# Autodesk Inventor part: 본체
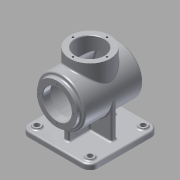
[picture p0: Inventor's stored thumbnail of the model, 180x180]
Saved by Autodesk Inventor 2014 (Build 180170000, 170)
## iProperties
Created: 2015-07
Part Number: 본체
Material: 알루미늄 6061
Document SubType Name: Modeling
Designer: L-10
Density: 2.71 g/cm^3
Appearance: 알루미늄 - 평지
Mass: 1277.36 g
Surface Area: 1268.17 cm^2
Volume: 471.35 cm^3
Author: L-10
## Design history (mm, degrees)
sketch "스케치2"
  geometry: C1 r 45 at (0, 0); 1 further point
  constraints: 1 centre point, 1 coincident
  dimensions: "d0" = 90 diameter of C1
extrude "돌출1" new body sketch "스케치2" stored distance "d1" = 110; taper "d2" = 0 deg
node "작업 평면1"
sketch "스케치3"
  geometry: L1 (-65, -65)-(65, -65); L2 (65, -65)-(65, 65); L3 (65, 65)-(-65, 65); L4 (-65, 65)-(-65, -65); 3 further points
  constraints: 8 end point, 2 midpoint, 2 parallel, 1 horizontal, 1 horizontal alignment, 1 perpendicular, 1 vertical alignment
  dimensions: "d4" = 130 distance of L2.end L3.end; "d5" = 130 distance of L3.end L1.start
extrude "돌출2" join sketch "스케치3" distance "d6" = 10; taper "d7" = 0 deg
sketch "스케치4"
  geometry: C1 r 45 at (0, 0) reference; C2 r 38 at (0, 0)
  constraints: 1 centre point, 1 coincident
  dimensions: "d8" = 76 diameter of C2
extrude "돌출3" join sketch "스케치4" distance "d9" = 7; taper "d10" = 0 deg
sketch "스케치5"
  geometry: L1 (-65, 65)-(-65, -65) reference; L2 (-5, 45)-(-5, 5); L3 (-5, 5)-(-45, 5); L4 (-45, 5)-(-45, -5); L5 (-45, -5)-(-5, -5); L6 (-5, -5)-(-5, -45); L7 (-5, -45)-(5, -45); L8 (5, -45)-(5, -5); L9 (5, -5)-(45, -5); L10 (45, -5)-(45, 5); L11 (45, 5)-(5, 5); L12 (5, 5)-(5, 45); L13 (5, 45)-(-5, 45); 3 further points
  constraints: 24 end point, 9 parallel, 6 collinear, 2 midpoint, 1 horizontal alignment, 1 perpendicular, 1 vertical alignment
  dimensions: "d11" = 10 distance of L9.end L10.end; "d12" = 10 distance of L12.end L2.start; "d13" = 90 distance between parallel lines of L7 L13; "d14" = 90 distance between parallel lines of L10 L4; "d15" = 45 distance from line of L4 point (0, 0) (= 0.5 x d14); "d16" = 45 distance from line of point (0, 0) L13 (= 0.5 x d13)
extrude "돌출4" join sketch "스케치5" stored distance "d17" = 7; taper "d18" = 0 deg
node "작업 평면2"
sketch "스케치6"
  geometry: C1 r 38 at (0, 0); 1 further point
  constraints: 1 centre point, 1 coincident
  dimensions: "d20" = 76 diameter of C1
extrude "돌출5" join sketch "스케치6" stored distance "d21" = 7; taper "d22" = 0 deg
fillet "모깎기1" dims "d23" = 15
sketch "스케치7"
  geometry: C1 r 7.5 at (50, -50); C2 r 7.5 at (50, 50); A1 r 15 centre (50, -50) between (50, -65) and (65, -50) reference; A2 r 15 centre (50, 50) between (65, 50) and (50, 65) reference; 1 further point
  constraints: 2 centre point, 2 coincident
  dimensions: "d24" = 15 diameter of C1; "d25" = 15 diameter of C2; "d26" = 100 distance of C2.centre C1.centre (derived)
extrude "돌출6" join sketch "스케치7" distance "d27" = 3; taper "d28" = 0 deg
hole "구멍1" diameter "d31" = 10; stored, may be unused: countersink angle "d35" = 90 deg, drill point angle "d37" = 118 deg; dims "d29" = 10, "d30" = 10, "d32" = 6, "d33" = 4, "d34" = 2, "d36" = 8
hole "구멍2" diameter "d40" = 10; stored, may be unused: countersink angle "d44" = 90 deg, drill point angle "d46" = 118 deg; dims "d38" = 10, "d39" = 10, "d41" = 6, "d42" = 4, "d43" = 2, "d45" = 8
hole "구멍3" diameter "d49" = 10; stored, may be unused: countersink angle "d53" = 90 deg, drill point angle "d55" = 118 deg; dims "d47" = 10, "d48" = 10, "d50" = 6, "d51" = 4, "d52" = 2, "d54" = 8
hole "구멍4" diameter "d58" = 10; stored, may be unused: countersink angle "d62" = 90 deg, drill point angle "d64" = 118 deg; dims "d56" = 10, "d57" = 10, "d59" = 6, "d60" = 4, "d61" = 2, "d63" = 8
sketch "스케치8"
  geometry: L1 (-62, 0)-(55, 0); L2 (-62, 38)-(-62, -38) reference; L3 (55, -45)-(55, 45) reference; L4 (-62, 27)-(-48, 27); L5 (-48, 27)-(-48, 40); L6 (-48, 40)-(48, 40); L7 (48, 40)-(48, 0); 2 further points
  constraints: 10 end point, 3 point on line, 2 midpoint, 2 parallel, 2 perpendicular, 1 horizontal, 1 horizontal alignment
  dimensions: "d65" = 80 diameter of L6 L1; "d66" = 7 distance between parallel lines of L3 L7; "d67" = 14 distance between parallel lines of L2 L5; "d68" = 54 diameter of L4 L1
revolve "회전1" sketch "스케치8" stored, may be unused: angle "d69" = 90 deg
hole "구멍5" diameter "d72" = 54; stored, may be unused: countersink angle "d76" = 90 deg, drill point angle "d78" = 118 deg; dims "d70" = 10, "d71" = 10, "d73" = 6, "d74" = 4, "d75" = 2, "d77" = 8
fillet "모깎기2" dims "d79" = 3
chamfer "모따기1" distance "d80" = 1; stored, may be unused: second distance "d81" = 2, angle "d82" = 45 deg
sketch "스케치9"
  geometry: C1 r 27 at (0, 0) reference; 1 further point
  constraints: 1 vertical alignment
  dimensions: "d83" = 32 distance of C1.centre point (0, 32)
hole "구멍6" sketch "스케치9" at (0, 32) diameter "d84" = 3.459; stored, may be unused: countersink angle "d88" = 90 deg, drill point angle "d90" = 118 deg; dims "d85" = 8, "d86" = 4, "d87" = 2, "d89" = 10
sketch "스케치10"
  geometry: C1 r 38 at (0, 0) reference; 1 further point
  constraints: 1 vertical alignment
  dimensions: "d94" = 32 distance of C1.centre point (0, 32)
hole "구멍7" sketch "스케치10" at (0, 32) diameter "d95" = 3.459; stored, may be unused: countersink angle "d99" = 90 deg, drill point angle "d101" = 118 deg; dims "d96" = 8, "d97" = 4, "d98" = 2, "d100" = 10
fillet "모깎기3" dims "d105" = 3
fillet "모깎기4" dims "d106" = 3
fillet "모깎기5" dims "d107" = 3
fillet "모깎기6" dims "d108" = 3
fillet "모깎기7" dims "d109" = 3
fillet "모깎기8" dims "d110" = 3
sketch "스케치11"
  geometry: C1 r 42 at (0, 0) reference; 1 further point
  constraints: 1 coincident, 1 other
feature "엠보싱1" sketch "스케치11" dims "d111" = 0.5, "d112" = 0
chamfer "모따기2" distance "d113" = 1; stored, may be unused: second distance "d114" = 2, angle "d115" = 45 deg
node "솔리드1"
mirror "대칭1"
pattern_circular "원형 패턴1" dims angle "d92" = 360 deg
pattern_circular "원형 패턴2" dims angle "d103" = 360 deg
other parameters: "d3" = -78
